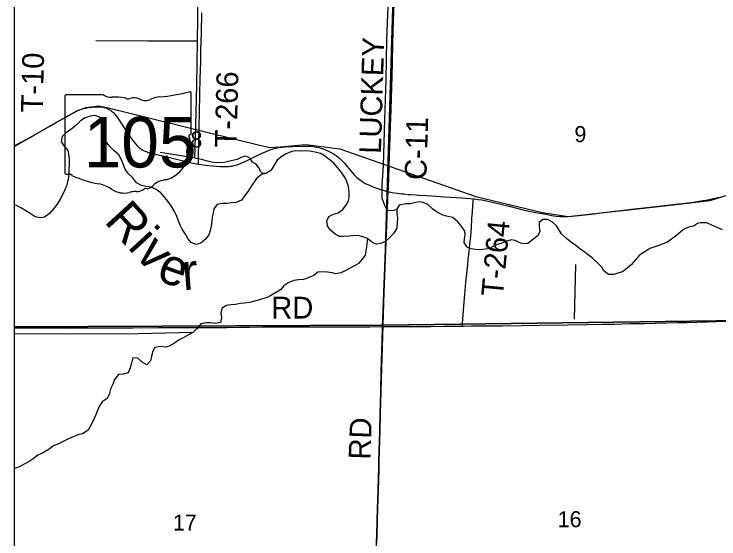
# Model space of a CAD drawing. Extents: x 0 to 34, y 0 to 22.
# Drawn here: x 2.1 to 3.939, y 15.963 to 17.332 of the extents above; entities that cross this region are included whole.
import ezdxf

# ---------------------------------------------------------------- set-up
doc = ezdxf.new("R2010")
doc.units = 0
for name, color, linetype in [('Default', 7, 'Continuous'), ('GM_X_County_Road', 7, 'Continuous'), ('GM_X_County_Road_Text', 7, 'Continuous'), ('GM_X_Major_River', 7, 'Continuous'), ('GM_X_Major_River_Text', 7, 'Continuous'), ('GM_X_Minor_River', 7, 'Continuous'), ('GM_X_Rail_Line', 7, 'Continuous'), ('GM_X_Section', 7, 'Continuous'), ('GM_X_Section_Text', 7, 'Continuous'), ('GM_X_State_Location', 7, 'Continuous'), ('GM_X_State_Route', 7, 'Continuous'), ('GM_X_State_Shield', 7, 'Continuous'), ('GM_X_Township_Road', 7, 'Continuous'), ('GM_X_Township_Road_Text', 7, 'Continuous'), ('SH_Cut_Line', 7, 'Continuous'), ('SH_Data', 7, 'Continuous')]:
    doc.layers.add(name, color=color, linetype=linetype)

msp = doc.modelspace()

# ---------------------------------------------------------------- linework, layer by layer
at = {"layer": 'Default'}
for points in [[(2.1, 20.9), (2.1, 15.5125)], [(3.0911, 17.385), (3.0884, 17.2887), (3.0874, 17.2514), (3.0863, 17.2079), (3.0852, 17.1706), (3.0824, 17.0836), (3.0809, 17.0401), (3.08, 17.0122), (3.0786, 16.9625), (3.0767, 16.9035), (3.0758, 16.8817), (3.0757, 16.8786), (3.0752, 16.87), (3.0611, 16.5175), (3.0609, 16.5105), (3.0598, 16.4794), (3.0586, 16.4265), (3.0578, 16.3985), (3.0565, 16.3519), (3.0556, 16.3115), (3.0552, 16.2959), (3.0547, 16.2804), (3.0539, 16.252), (3.0529, 16.2119), (3.0527, 16.1993), (3.0524, 16.1873), (3.0518, 16.1685), (3.0512, 16.1437), (3.0503, 16.1157), (3.0488, 16.0659), (3.0479, 16.041), (3.0472, 16.013), (3.0461, 15.9726), (3.0454, 15.9508)], [(3.0454, 15.9508), (3.0461, 15.9726), (3.0472, 16.013), (3.0479, 16.041), (3.0488, 16.0659), (3.0503, 16.1157), (3.0512, 16.1437), (3.0518, 16.1685), (3.0524, 16.1873), (3.0527, 16.1993), (3.0529, 16.2119), (3.0539, 16.252), (3.0547, 16.2804), (3.0552, 16.2959), (3.0556, 16.3115), (3.0565, 16.3519), (3.0578, 16.3985), (3.0586, 16.4265), (3.0598, 16.4794), (3.0609, 16.5105), (3.0611, 16.5175), (3.0752, 16.87), (3.0757, 16.8786), (3.0758, 16.8817), (3.0767, 16.9035), (3.0786, 16.9625), (3.08, 17.0122), (3.0809, 17.0401), (3.0824, 17.0836), (3.0852, 17.1706), (3.0863, 17.2079), (3.0874, 17.2514), (3.0884, 17.2887), (3.0911, 17.385)]]:
    msp.add_lwpolyline(points, dxfattribs=at)
for points in [[(2.1, 17.5151), (2.1, 16.5162), (3.0627, 16.5204), (3.0931, 17.5206)], [(2.1, 16.5162), (2.1, 15.5152), (3.0319, 15.521), (3.0627, 16.5204)]]:
    msp.add_lwpolyline(points, close=True, dxfattribs=at)
at = {"layer": 'GM_X_County_Road'}
msp.add_lwpolyline([(3.0754, 16.8694), (3.0759, 16.8781), (3.0761, 16.8812), (3.077, 16.9029), (3.0788, 16.9619), (3.0802, 17.0116), (3.0811, 17.0396), (3.0826, 17.0831), (3.0854, 17.1701), (3.0866, 17.2073), (3.0876, 17.2508), (3.0886, 17.2881), (3.0914, 17.3844), (3.0943, 17.4931), (3.0949, 17.5166)], dxfattribs=at)
at = {"layer": 'GM_X_Major_River'}
for points in [[(2.7189, 16.8841), (2.7103, 16.8706), (2.7017, 16.859), (2.6928, 16.847), (2.6793, 16.8404), (2.6668, 16.8395), (2.655, 16.8386), (2.6429, 16.8381), (2.6295, 16.8353), (2.621, 16.8241), (2.6189, 16.8138), (2.6164, 16.8021), (2.6158, 16.7918), (2.6137, 16.7793), (2.6116, 16.768), (2.6076, 16.7567), (2.599, 16.7447), (2.5874, 16.735), (2.5748, 16.7314), (2.562, 16.7362), (2.5531, 16.7471), (2.5469, 16.7578), (2.5388, 16.7709), (2.5336, 16.7813), (2.5282, 16.795), (2.5235, 16.8069), (2.5184, 16.8173), (2.5099, 16.8323), (2.501, 16.8442), (2.4929, 16.8539), (2.4829, 16.8662), (2.4709, 16.8748), (2.4581, 16.8804), (2.4441, 16.8829), (2.432, 16.8854), (2.4192, 16.8921), (2.41, 16.9049), (2.398, 16.9165), (2.3888, 16.9296), (2.3852, 16.9392), (2.3801, 16.9522), (2.3728, 16.9652), (2.3608, 16.9757), (2.3493, 16.9877), (2.3381, 17.0012), (2.3327, 17.0139), (2.3321, 17.0261), (2.3335, 17.039), (2.3326, 17.0519), (2.3234, 17.0639), (2.3105, 17.0679), (2.2984, 17.0662), (2.2857, 17.0615), (2.2731, 17.0538), (2.2607, 17.0419), (2.248, 17.0311), (2.2365, 17.0233), (2.2253, 17.0129), (2.2227, 17.0004), (2.2301, 16.9885), (2.2398, 16.9765), (2.2422, 16.967), (2.2435, 16.9544), (2.244, 16.9407), (2.243, 16.9274), (2.2424, 16.916), (2.2419, 16.9062), (2.2397, 16.8944), (2.2365, 16.8846), (2.2325, 16.8737), (2.2266, 16.8605), (2.2203, 16.8496), (2.2125, 16.8364), (2.2031, 16.8244), (2.1923, 16.8125), (2.1796, 16.8025), (2.1682, 16.8008), (2.1553, 16.8033), (2.1422, 16.8119), (2.1306, 16.819), (2.1189, 16.8264), (2.1062, 16.8331), (2.1, 16.8336)], [(3.0813, 16.7502), (3.0693, 16.7399), (3.057, 16.7334), (3.0453, 16.7317), (3.0355, 16.7358), (3.0222, 16.7471), (3.0074, 16.7522), (2.9951, 16.7546), (2.9829, 16.7541), (2.9731, 16.7532), (2.9598, 16.7524), (2.9492, 16.7523), (2.9372, 16.7579), (2.9246, 16.7696), (2.9173, 16.7796), (2.9159, 16.7928), (2.9213, 16.8042), (2.9332, 16.8107), (2.9454, 16.8135), (2.9578, 16.8227), (2.9675, 16.8353), (2.9723, 16.8455), (2.9741, 16.8553), (2.9744, 16.8686), (2.9725, 16.8823), (2.9679, 16.8957), (2.9636, 16.9053), (2.9552, 16.9184), (2.9449, 16.9311), (2.9335, 16.944), (2.9209, 16.9537), (2.9101, 16.9624), (2.8996, 16.9683), (2.885, 16.9721), (2.8706, 16.9751), (2.8582, 16.9758), (2.846, 16.9745), (2.8343, 16.9756), (2.8244, 16.9735), (2.8083, 16.9671), (2.7987, 16.9609), (2.786, 16.9509), (2.7781, 16.9386), (2.7702, 16.9251), (2.7575, 16.9167), (2.7453, 16.914), (2.7322, 16.9033), (2.7189, 16.8841)], [(3.9479, 16.7699), (3.9355, 16.7747), (3.9216, 16.7811), (3.9074, 16.7879), (3.8908, 16.7879), (3.8824, 16.7859), (3.872, 16.7789), (3.859, 16.7762), (3.846, 16.7701), (3.834, 16.7601), (3.8244, 16.752), (3.8147, 16.745), (3.8024, 16.7362), (3.7905, 16.7319), (3.7794, 16.728), (3.7691, 16.7241), (3.7588, 16.7206), (3.745, 16.7122), (3.7315, 16.7034), (3.7202, 16.69), (3.7097, 16.6781), (3.6996, 16.6692), (3.6872, 16.6597), (3.6777, 16.6569), (3.6647, 16.653), (3.6507, 16.6526), (3.6381, 16.6624), (3.633, 16.672), (3.6212, 16.684), (3.6086, 16.6954), (3.5982, 16.7032), (3.5863, 16.713), (3.5759, 16.7197), (3.5648, 16.7291), (3.5551, 16.7357), (3.5421, 16.7463), (3.5284, 16.7592), (3.5222, 16.7688), (3.5153, 16.7796), (3.5049, 16.7893), (3.4922, 16.7965), (3.4793, 16.7968), (3.4697, 16.789), (3.4697, 16.7761), (3.4714, 16.7658), (3.4673, 16.7546), (3.4519, 16.7435), (3.4399, 16.734), (3.4304, 16.7327), (3.4206, 16.7344), (3.4075, 16.7416), (3.3974, 16.7437), (3.3828, 16.7388), (3.3698, 16.7338), (3.3603, 16.731), (3.35, 16.7259), (3.34, 16.7208), (3.3301, 16.7188), (3.3149, 16.7173), (3.3032, 16.7183), (3.2911, 16.7197), (3.2806, 16.7255), (3.2737, 16.7365), (3.2747, 16.7463), (3.2769, 16.7565), (3.276, 16.766), (3.2661, 16.7799), (3.2573, 16.7904), (3.2443, 16.8013), (3.2281, 16.8048), (3.2166, 16.809), (3.2019, 16.8168), (3.1922, 16.8231), (3.1792, 16.8352), (3.1672, 16.8408), (3.1574, 16.8429), (3.1437, 16.8402), (3.1331, 16.837), (3.1217, 16.8369), (3.1042, 16.834), (3.098, 16.8233), (3.0987, 16.8121), (3.1, 16.8006), (3.0993, 16.7878), (3.0982, 16.7741), (3.091, 16.761), (3.0813, 16.7502)]]:
    msp.add_lwpolyline(points, dxfattribs=at)
at = {"layer": 'GM_X_Minor_River'}
for points in [[(3.098, 16.8233), (3.0903, 16.8196), (3.081, 16.8188), (3.0728, 16.8206), (3.0667, 16.8326), (3.0603, 16.8517), (3.0604, 16.8862), (3.0636, 16.9374), (3.0673, 17.0565), (3.071, 17.1611), (3.0721, 17.2651), (3.0773, 17.397), (3.0802, 17.5617), (3.0826, 17.6891), (3.0877, 17.8181), (3.0919, 17.9424), (3.0953, 18.0486), (3.1003, 18.2212), (3.1054, 18.3486), (3.1085, 18.4912)], [(2.5711, 16.9562), (2.5739, 17.0409), (2.5765, 17.1473), (2.5787, 17.2621), (2.5798, 17.3814), (2.5828, 17.5004), (2.587, 17.62), (2.5899, 17.7374), (2.5928, 17.84), (2.5951, 17.9312), (2.5981, 18.0258), (2.5002, 18.0267), (2.4979, 18.0123), (2.4967, 18.0085), (2.4913, 18.0064), (2.3041, 18.0053), (2.1766, 18.0059), (2.1151, 18.0065), (2.1, 18.0065)], [(2.5787, 17.2621), (2.4492, 17.262), (2.3133, 17.2625)], [(2.7221, 16.9464), (2.7168, 16.9547), (2.7124, 16.9583), (2.7045, 16.9615), (2.6945, 16.9588), (2.6822, 16.9534), (2.6666, 16.9493), (2.649, 16.9456), (2.6345, 16.9445), (2.6194, 16.9453), (2.6047, 16.9488), (2.5885, 16.9531), (2.5711, 16.9562), (2.5413, 16.9617), (2.4808, 16.9714)], [(2.7575, 16.9167), (2.7473, 16.9177), (2.7428, 16.922), (2.7389, 16.9301), (2.7334, 16.9378), (2.7278, 16.9425), (2.7221, 16.9464)], [(3.0222, 16.7471), (3.019, 16.7256), (3.0179, 16.7134), (3.0154, 16.7036), (3.0071, 16.6917), (2.9986, 16.6816), (2.9832, 16.6725), (2.9736, 16.6678), (2.9621, 16.6617), (2.9525, 16.6569), (2.9396, 16.6546), (2.9294, 16.6571), (2.9177, 16.6589), (2.9041, 16.66), (2.8927, 16.6588), (2.8823, 16.6503), (2.8674, 16.6438), (2.8551, 16.6396), (2.8415, 16.6388), (2.8301, 16.6375), (2.8171, 16.6318), (2.804, 16.6237), (2.7962, 16.614), (2.7866, 16.6074), (2.7719, 16.5987), (2.7604, 16.5929), (2.7482, 16.589), (2.7372, 16.5855), (2.7141, 16.5799)], [(3.5646, 16.6786), (3.5611, 16.536)], [(2.7141, 16.5799), (2.7008, 16.578), (2.6909, 16.5768), (2.6772, 16.5749), (2.665, 16.5737), (2.6528, 16.5718), (2.6416, 16.5645), (2.6393, 16.552), (2.6408, 16.5394), (2.6382, 16.5277), (2.6253, 16.5254), (2.6132, 16.5269), (2.5999, 16.5269), (2.5873, 16.5242), (2.5774, 16.5123), (2.5661, 16.5013), (2.553, 16.4944), (2.5407, 16.4872), (2.531, 16.4825), (2.5183, 16.4741), (2.5047, 16.4658), (2.4948, 16.4634), (2.4808, 16.4649), (2.4671, 16.4626), (2.4615, 16.4529), (2.4585, 16.4397), (2.4558, 16.4272), (2.4464, 16.4172), (2.4345, 16.424), (2.423, 16.4343), (2.4101, 16.435), (2.4059, 16.4211), (2.4025, 16.409), (2.3972, 16.3962), (2.3846, 16.3932), (2.3724, 16.392), (2.3615, 16.379), (2.3585, 16.3688), (2.3516, 16.3542), (2.349, 16.3421), (2.3426, 16.3297), (2.3294, 16.3206), (2.3222, 16.3082), (2.3125, 16.285), (2.3072, 16.2726), (2.3, 16.2598), (2.2931, 16.2463), (2.2785, 16.2373), (2.267, 16.2345), (2.254, 16.2296), (2.2416, 16.2243), (2.2281, 16.2167), (2.2174, 16.212), (2.2028, 16.2056), (2.1888, 16.1953), (2.1738, 16.187), (2.1622, 16.1817), (2.1498, 16.1721), (2.137, 16.163), (2.1266, 16.158), (2.1128, 16.1508), (2.1, 16.1458)], [(2.5661, 16.5013), (2.4233, 16.4977), (2.2441, 16.4968), (2.1, 16.4977)]]:
    msp.add_lwpolyline(points, dxfattribs=at)
at = {"layer": 'GM_X_Rail_Line'}
msp.add_lwpolyline([(2.1, 16.989), (2.137, 17.008), (2.2064, 17.0481), (2.2635, 17.0798), (2.2874, 17.0883), (2.3198, 17.0929), (2.3422, 17.089), (2.7364, 16.991), (2.7673, 16.9841), (2.7943, 16.9864), (2.8612, 16.9919), (2.9494, 16.9811), (3.3041, 16.8562), (3.4786, 16.8144), (3.5457, 16.804), (3.7963, 16.8323), (3.9156, 16.8457), (4.0662, 16.8935), (4.562, 17.1188)], dxfattribs=at)
at = {"layer": 'GM_X_Section'}
for points in [[(4.0852, 17.5486), (4.0656, 16.5335), (3.0627, 16.5204), (3.0931, 17.5206)], [(3.0627, 16.5204), (4.0656, 16.5335), (4.0396, 15.5284), (3.0319, 15.521)]]:
    msp.add_lwpolyline(points, close=True, dxfattribs=at)
at = {"layer": 'GM_X_State_Route'}
for points in [[(2.2454, 17.0699), (2.2533, 17.0743), (2.2579, 17.0767), (2.2622, 17.0788), (2.2675, 17.0812), (2.2717, 17.0828), (2.2762, 17.0843), (2.2817, 17.0861), (2.2872, 17.0874), (2.2935, 17.0886), (2.2984, 17.0892), (2.3026, 17.0897), (2.3068, 17.0902), (2.3113, 17.0906), (2.3164, 17.0908), (2.3199, 17.0908), (2.323, 17.0907), (2.3262, 17.0904), (2.3305, 17.0899), (2.3345, 17.089), (2.3383, 17.0879), (2.3417, 17.0867), (2.3445, 17.0855), (2.3474, 17.0839), (2.3517, 17.0814), (2.3543, 17.0795), (2.3567, 17.0777), (2.3591, 17.0754), (2.3612, 17.0733), (2.363, 17.0713), (2.3666, 17.0669), (2.3709, 17.0608)], [(2.1, 16.9872), (2.1037, 16.9891), (2.1383, 17.0087), (2.1533, 17.0176), (2.1668, 17.0251), (2.1934, 17.0401), (2.208, 17.0484), (2.2328, 17.0626), (2.2419, 17.068), (2.2454, 17.0699)], [(2.3709, 17.0608), (2.3822, 17.0436), (2.397, 17.0206), (2.4045, 17.0099), (2.4127, 16.999), (2.4177, 16.9927), (2.4218, 16.9882), (2.4258, 16.9844), (2.4296, 16.9813), (2.4342, 16.9783), (2.4391, 16.9757), (2.4442, 16.9735), (2.4494, 16.9717), (2.4567, 16.9695), (2.4638, 16.9678), (2.4833, 16.9635), (2.505, 16.9586), (2.5636, 16.9445), (2.5758, 16.942), (2.5808, 16.9411), (2.588, 16.9399), (2.599, 16.9385), (2.6178, 16.9366), (2.6371, 16.9351), (2.6442, 16.9348), (2.6516, 16.9346), (2.656, 16.9348), (2.6601, 16.9351), (2.6639, 16.9356), (2.6671, 16.936), (2.6719, 16.9368), (2.6764, 16.9379), (2.6812, 16.9393), (2.6864, 16.9412), (2.692, 16.9435), (2.7025, 16.9482), (2.7182, 16.9557), (2.7361, 16.9643), (2.7492, 16.9703), (2.76, 16.975), (2.7652, 16.977), (2.7699, 16.9787), (2.7743, 16.9803), (2.7783, 16.9814), (2.7832, 16.9826), (2.7906, 16.9839), (2.7993, 16.9851), (2.8067, 16.9858), (2.8272, 16.9868), (2.8521, 16.9877), (2.8621, 16.988), (2.8702, 16.9879), (2.8748, 16.9876), (2.8796, 16.9871), (2.8845, 16.9864), (2.8888, 16.9854), (2.8949, 16.9841), (2.8994, 16.9828), (2.9033, 16.9816), (2.9067, 16.9804), (2.9104, 16.979), (2.9142, 16.9775), (2.9182, 16.9757), (2.922, 16.9739), (2.9257, 16.972), (2.9288, 16.9703), (2.9317, 16.9686), (2.935, 16.9666), (2.9381, 16.9645), (2.941, 16.9624), (2.9441, 16.9601), (2.947, 16.9578), (2.9499, 16.9552), (2.9553, 16.9501), (2.9609, 16.9441), (2.9685, 16.9351), (2.9822, 16.9189), (2.988, 16.9125), (2.991, 16.9095), (2.9932, 16.9073), (2.9982, 16.9028), (3.0042, 16.8981), (3.0097, 16.8945), (3.016, 16.8908), (3.0225, 16.8877), (3.0285, 16.885), (3.0338, 16.8828), (3.0384, 16.8811), (3.0433, 16.8793), (3.0495, 16.877), (3.0561, 16.8748), (3.0625, 16.8728), (3.0705, 16.8706), (3.0754, 16.8694)], [(3.0754, 16.8694), (3.0808, 16.8682), (3.0863, 16.8671), (3.0917, 16.8661), (3.0991, 16.865), (3.1047, 16.8643), (3.1104, 16.8636), (3.1165, 16.863), (3.1281, 16.8621), (3.1342, 16.8616), (3.1491, 16.8606), (3.1553, 16.8602), (3.1764, 16.8587), (3.1896, 16.8578), (3.2, 16.857), (3.2119, 16.8563), (3.2217, 16.8557), (3.2372, 16.8547), (3.2688, 16.8527), (3.2986, 16.8504), (3.3107, 16.849), (3.32, 16.8475), (3.3322, 16.845), (3.3549, 16.8397), (3.3731, 16.8355), (3.3913, 16.8311), (3.4244, 16.8229), (3.4426, 16.8186), (3.4608, 16.8149), (3.4868, 16.81), (3.5021, 16.8073), (3.5144, 16.8055), (3.5251, 16.8043), (3.5344, 16.8039), (3.5437, 16.804), (3.5545, 16.8048), (3.573, 16.8067), (3.607, 16.8107), (3.6378, 16.8143), (3.6594, 16.817), (3.6826, 16.8199), (3.7104, 16.823), (3.7506, 16.8275), (3.8262, 16.8362), (3.8509, 16.8391), (3.8725, 16.842), (3.897, 16.8459), (3.9047, 16.8472), (3.9199, 16.8501), (3.932, 16.8528), (3.944, 16.8559)]]:
    msp.add_lwpolyline(points, dxfattribs=at)
at = {"layer": 'GM_X_State_Shield'}
for p, q in [((2.2325, 17.1183), (2.2325, 16.9181)), ((2.3323, 17.1217), (2.2358, 17.1217)), ((2.5621, 17.022), (2.5621, 17.1267)), ((2.5621, 17.022), (2.5621, 17.022))]:
    msp.add_line(p, q, dxfattribs=at)
for centre, major_axis, start_param, end_param in [((2.2363, 17.1187), (0.00382, 0), 1.712693, 3.28349), ((2.3553, 17.1449), (0.037, 0), 4.042523, 4.731795), ((2.4447, 17.3945), (0.3495, 0), 4.814394, 5.042369), ((2.5584, 17.1271), (0.00367, 0), 6.141152, 7.989035), ((2.3675, 17.0093), (0.133, 0), 1.404758, 1.657858), ((2.3977, 17.1197), (0.0107, 0), 3.836095, 5.185415), ((2.4134, 17.0966), (0.0222, 0), 0.950623, 2.079405), ((2.4421, 17.1283), (0.0267, 0), 4.081561, 5.145723), ((2.4893, 17.0606), (0.0703, 0), 1.699011, 2.107814), ((2.5612, 17.0143), (0.00568, 0), 1.883978, 3.671073), ((2.5251, 17.0011), (0.0341, 0), 5.934695, 6.695948), ((2.5582, 17.0216), (0.00393, 0), 5.05454, 6.418171), ((2.5752, 16.9782), (0.0248, 0), 2.387724, 3.262537), ((2.4643, 16.9648), (0.0874, 0), 5.101752, 6.440018), ((2.2363, 16.9177), (0.00385, 0), 3.00124, 4.508301), ((2.2369, 16.9382), (0.0294, 0), 4.665946, 4.897461), ((2.2429, 16.9066), (0.0106, 0), 0.519207, 1.627899), ((2.3767, 17.0864), (0.2524, 0), 4.195997, 4.488961), ((2.5011, 16.8619), (0.0479, 0), 1.647645, 2.488434), ((2.3015, 16.8282), (0.079, 0), 0.823519, 1.323587), ((2.4405, 16.8987), (0.0282, 0), 4.937069, 5.64225), ((2.3869, 16.9056), (0.0501, 0), 4.026481, 4.996735), ((2.4159, 16.8364), (0.0412, 0), 1.495662, 1.94098), ((2.4195, 16.8906), (0.0267, 0), 4.691044, 5.507374), ((2.4437, 16.8712), (0.00752, 0), 1.147584, 2.315152)]:
    msp.add_ellipse(centre, major_axis=major_axis, ratio=0.8, start_param=start_param, end_param=end_param, dxfattribs=at)
at = {"layer": 'GM_X_Township_Road'}
for points in [[(2.5808, 16.9411), (2.5808, 16.9468), (2.5809, 16.9548), (2.5819, 17.0062), (2.5835, 17.0746), (2.5846, 17.1243), (2.5858, 17.1648), (2.5868, 17.2083), (2.5875, 17.2394), (2.5886, 17.2829), (2.5899, 17.3356)], [(3.288, 16.7206), (3.2892, 16.7314), (3.2912, 16.7531), (3.2928, 16.7748), (3.2944, 16.7997), (3.2954, 16.8153), (3.2968, 16.834), (3.2986, 16.8504)], [(3.2694, 16.5184), (3.2696, 16.5215), (3.2698, 16.525), (3.2732, 16.57), (3.2757, 16.6011), (3.2787, 16.6321), (3.282, 16.6631), (3.2835, 16.6787), (3.2848, 16.6911), (3.288, 16.7206)], [(3.2694, 16.5184), (3.2739, 16.5184), (3.2928, 16.5186), (3.3736, 16.5193), (3.4233, 16.5201), (3.4699, 16.5208), (3.5445, 16.5219), (3.5943, 16.5228), (3.6346, 16.5232), (3.6657, 16.5237), (3.7061, 16.5246), (3.7434, 16.5254), (3.8304, 16.5272), (3.8553, 16.5277), (3.9081, 16.5292), (3.9578, 16.5307), (3.9889, 16.5315), (4.0386, 16.5331), (4.0603, 16.5335), (4.0626, 16.5336)], [(2.1, 16.5133), (2.1391, 16.5134), (2.2106, 16.5137), (2.2758, 16.5138), (2.3131, 16.514), (2.3504, 16.514), (2.4095, 16.514), (2.4778, 16.5144), (2.5119, 16.5143), (2.533, 16.5144), (2.5719, 16.5146), (2.6239, 16.5148), (2.655, 16.515), (2.6829, 16.5156), (2.714, 16.5158), (2.7482, 16.516), (2.7948, 16.5159), (2.8383, 16.5159), (2.9284, 16.5161), (2.9813, 16.5162), (3.0279, 16.5165), (3.0614, 16.5169)], [(3.0457, 15.9502), (3.0463, 15.972), (3.0475, 16.0125), (3.0481, 16.0405), (3.049, 16.0653), (3.0505, 16.1151), (3.0514, 16.1431), (3.0521, 16.168), (3.0527, 16.1868), (3.0529, 16.1987), (3.0531, 16.2113), (3.0541, 16.2514), (3.0549, 16.2798), (3.0554, 16.2954), (3.0558, 16.3109), (3.0567, 16.3513), (3.0581, 16.398), (3.0589, 16.426), (3.06, 16.4789), (3.0611, 16.51), (3.0614, 16.5169)], [(3.0614, 16.5169), (3.0683, 16.517), (3.1465, 16.5176), (3.1871, 16.5176), (3.2213, 16.5181), (3.2555, 16.5182), (3.2694, 16.5184)]]:
    msp.add_lwpolyline(points, dxfattribs=at)
at = {"layer": 'SH_Cut_Line'}
msp.add_lwpolyline([(7.1734, 20.9), (2.1, 20.9), (2.1, 14.1)], dxfattribs=at)
at = {"layer": 'SH_Data'}
msp.add_line((2.1, 20.9), (2.1, 14.1), dxfattribs=at)

# ---------------------------------------------------------------- texts
at = {"layer": 'GM_X_County_Road_Text'}
for s, rotation, p in [('LUCKEY', 88.3106, (3.0569, 16.9673)), ('C-11', 88.2741, (3.1754, 16.8989))]:
    msp.add_text(s, height=0.05682, rotation=rotation, dxfattribs=at).set_placement(p)
at = {"layer": 'GM_X_Major_River_Text'}
for s, height, rotation, p in [('Riv', 0.09476, 312.4276, (2.3327, 16.7906)), ('e', 0.0948, 340.4288, (2.4687, 16.6393)), ('r', 0.0948, 4.4307, (2.5409, 16.6117))]:
    msp.add_text(s, height=height, rotation=rotation, dxfattribs=at).set_placement(p)
at = {"layer": 'GM_X_Section_Text'}
for s, height, p in [('8', 0.0419, (2.5601, 16.9842)), ('9', 0.0419, (3.5617, 16.9984)), ('16', 0.04186, (3.518, 15.9934)), ('17', 0.04186, (2.5142, 15.9847))]:
    msp.add_text(s, height=height, rotation=0, dxfattribs=at).set_placement(p)
at = {"layer": 'GM_X_State_Location'}
msp.add_text('105', height=0.000189, rotation=0, dxfattribs=at).set_placement((2.3267, 16.9911))
for s in ['s', 'r']:
    msp.add_text(s, height=0.000189, dxfattribs=at).set_placement((2.3936, 17.0049))
at = {"layer": 'GM_X_State_Shield'}
msp.add_text('105', height=0.13184, dxfattribs=at).set_placement((2.2816, 16.9322))
at = {"layer": 'GM_X_Township_Road_Text'}
for s, rotation, p in [('T-10', 88.585, (2.1745, 17.0751)), ('T-266', 88.6099, (2.6803, 16.9839)), ('T-264', 84.6793, (3.3749, 16.5933)), ('RD', 0, (2.7709, 16.538)), ('RD', 88.0242, (3.0294, 16.1691))]:
    msp.add_text(s, height=0.05682, rotation=rotation, dxfattribs=at).set_placement(p)

doc.saveas('drawing.dxf')
